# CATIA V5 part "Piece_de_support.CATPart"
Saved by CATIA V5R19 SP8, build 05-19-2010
Part number: Piece_de_support
Bounding box of the stored display mesh (mm): x -170 to 170, y -44 to 314.998, z 1111.393 to 1414.998
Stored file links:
  G:\EU_thinkMotion\CFAO_2010\MMS_groupe2\MMS_groupe2\OK\nrosalie\nrosalie_cfao_support_d_arme_legere_final\Piece_de_support.CATPart
  G:\EU_thinkMotion\CFAO_2010\MMS_groupe2\MMS_groupe2\OK\nrosalie\nrosalie_cfao_support_d_arme_legere_final\nrosalie_Support_d_arme_legere.CATProduct
  G:\EU_thinkMotion\CFAO_2010\MMS_groupe2\MMS_groupe2\OK\nrosalie\nrosalie_cfao_support_d_arme_legere_final\Squelette_Colone.CATPart
  G:\EU_thinkMotion\CFAO_2010\MMS_groupe2\MMS_groupe2\OK\nrosalie\nrosalie_cfao_support_d_arme_legere_final\NAO_40x55x17_PART2.CATPart
  G:\EU_thinkMotion\CFAO_2010\MMS_groupe2\MMS_groupe2\OK\nrosalie\nrosalie_cfao_support_d_arme_legere_final\NKX_45_PART1.CATPart
  G:\EU_thinkMotion\CFAO_2010\MMS_groupe2\MMS_groupe2\OK\nrosalie\nrosalie_cfao_support_d_arme_legere_final\Entretoise_d_usure.CATPart
  G:\EU_thinkMotion\CFAO_2010\MMS_groupe2\MMS_groupe2\OK\nrosalie\nrosalie_cfao_support_d_arme_legere_final\Squelette_Systeme_de_visee.CATPart
  G:\EU_thinkMotion\CFAO_2010\MMS_groupe2\MMS_groupe2\OK\nrosalie\nrosalie_cfao_support_d_arme_legere_final\Squelette_piece_support.CATPart
  G:\EU_thinkMotion\CFAO_2010\MMS_groupe2\MMS_groupe2\OK\nrosalie\nrosalie_cfao_support_d_arme_legere_final\Squelette_systeme_d_equilibrage.CATPart
  C:\Program Files\Dassault Systemes\B19\intel_a\startup\materials\French\Catalog.CATMaterial
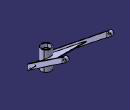
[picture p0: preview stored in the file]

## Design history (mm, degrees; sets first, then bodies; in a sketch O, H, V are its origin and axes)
Set1
  Sketch1 on zx-plane, origin (0, 0, 0), H (-1, 0, 0), V (0, 0, 1)
    line L1 (27.5, 1249) -> (27.5, 1223)
    line L2 (27.5, 1223) -> (25.7071, 1223)
    line L3 (25, 1222.2929) -> (25, 1130.1001)
    line L4 (25.7071, 1129.393) -> (29, 1129.393)
    line L5 (29, 1129.393) -> (29, 1112.1001)
    line L6 (29.7071, 1111.393) -> (34, 1111.393)
    point P4 (34, 1111.393)
    line L7 (27.5, 1249) -> (34, 1249)
    line L8 (34, 1249) -> (34, 1111.393)
    point P6 (34, 1111.393)
    reference projected line E1 (0, 0) -> (0, 1300) from Line1
    line L9 (25.7071, 1223) -> (25, 1222.2929)
    line L10 (25, 1130.1001) -> (25.7071, 1129.393)
    line L11 (29, 1112.1001) -> (29.7071, 1111.393)
    reference projected line E2 (0, 0) -> (0, 1300) from Line1
    reference projected line E3 (0, 0) -> (0, 1300) from Line1
    reference intersected line E4 through (0, 1250) direction (-1, 0) from Plane1
    reference intersected line E5 through (0, 1223) direction (-1, 0) from face of DatumSurface1
    reference intersected line E6 through (0, 1129.393) direction (1, 0) from face of DatumSurface2
    reference intersected line E7 through (0, 1111.393) direction (1, 0) from face of DatumSurface3
    distance L3 E1 = 25
    angle L2 L9 = 45
    length L9 = 1
    angle L3 L10 = 45
    length L10 = 1
    angle L5 L11 = 45
    length L11 = 1
    distance L5 E2 = 29
    distance L1 E3 = 27.5
    distance L8 L5 = 5
    distance L7 E4 = 1
    vertical: L1 V, L3 V, L5 V, L8 V
    horizontal: L2 H, L4 H, L6 H, L7 H
    coincidence: P4 P6, L2 E5, L4 E6, L6 E7
Set2
  Plane1 "Plan_limite_superieur_colonne": linked copy from another document
  DatumSurface1 to DatumSurface3: linked copy from another document
  Line1 "Axe_vertical_colonne": linked copy from another document
  Point1 "Centre_plan_limite_superieur_colonne": linked copy from another document
  DatumCurve1: linked copy from another document
  Plane2: linked copy from another document
  Line2: linked copy from another document
  Line3 "Axe_de_rotation_en_site": linked copy from another document
  Plane3 "Interphase_pivot_permettant _la_rotation_en_site": linked copy from another document
  Point2 "Centre_cou_du_servant": linked copy from another document
  Point3 "Centre_liaison_pivot__systeme_de_visee": linked copy from another document
  Plane4: linked copy from another document
  Point4: linked copy from another document
  Point5 "intersection_axe_colone_et_axe_viseur": linked copy from another document
  Line4: linked copy from another document
  Plane5 "Plan_horizontal_median_viseur": linked copy from another document
  Point6: linked copy from another document
  Line5: linked copy from another document
Body1 (main body)
  Shaft1: profile Sketch1, axis edge of Line1, angle 360
  Sketch2 on zx-plane, origin (0, 0, 0), H (-1, 0, 0), V (0, 0, 1)
    circle A1 centre (-0.0003, 1120.393) radius 0.79
    reference projected circle E1 centre (-0.0003, 1120.393) radius 0.79 from edge of DatumCurve1
    coincidence: E1 A1
  Pocket1: profile Sketch2, direction (0, 1, 0), length 2000
  Sketch3 on yz-plane, origin (0, 0, 0), H (0, 1, 0), V (0, 0, 1)
    line L1 (309, 1388) -> (-44, 1123.25)
    point P1 (-44, 1123.25)
    point P2 (-44, 1123.25)
    line L2 (-44, 1160.75) -> (291, 1412)
    reference projected line E1 (11.8125, 1183.8594) -> (396, 1472) from Line2
    arc A1 centre (300, 1400) radius 15 from (309, 1388) to (291, 1412) ccw
    reference projected point E2 (300, 1400) from Point2
    line L3 (-44, 1160.75) -> (-44, 1123.25)
    reference projected point E3 (0, 1175) from Point3
    radius A1 = 15
    distance E3 L3 = 44
    coincidence: P2 L1, P2 P1
    parallelism: L2 L1
    symmetry: L2 L1 E1
    concentricity: A1 E2
    tangency: L2 A1
    vertical: L3 V
  Sketch4 on Plane2, origin (0, 0, 1175), H (1, 0, 0), V (0, 1, 0)
    line L1 (-166.7686, 285) -> (-85.1019, -65)
    point P2 (-85.1019, -65)
    line L2 (-76, -60) -> (-156.5, 285)
    point P3 (-76, -60)
    point P4 (-156.5, 285)
    line L3 (-166.7686, 285) -> (-170, 285)
    line L4 (-170, 285) -> (-170, 315)
    line L5 (-170, 315) -> (-150, 315)
    line L6 (-150, 315) -> (-150, 285)
    line L7 (-156.5, 285) -> (-150, 285)
    point P9 (-156.5, 285)
    reference projected line E1 (-500, 300) -> (500, 300) from Line3
    reference projected line E2 (-500, 300) -> (500, 300) from Line3
    reference projected line E3 (-88.8296, -5.016) -> (-160, 300) from Line2
    reference intersected line E4 through (-150, 0) direction (0, 1) from Plane3
    reference projected point E5 (0, 0) from Point5
    line L8 (150, 315) -> (150, 285)
    line L9 (150, 285) -> (156.5, 285)
    line L10 (156.5, 285) -> (76, -60)
    point P13 (76, -60)
    point P14 (85.1019, -65)
    line L11 (85.1019, -65) -> (166.7686, 285)
    point P15 (166.7686, 285)
    line L12 (166.7686, 285) -> (170, 285)
    line L13 (170, 315) -> (170, 285)
    line L14 (170, 315) -> (150, 315)
    reference projected line E6 (0, 300) -> (0, 0) from Line4
    reference projected point E7 (0, 300) from Point2
    reference projected line E9 (0, 300) -> (0, 0) from Line4
    reference projected line E10 (0, 300) -> (0, 0) from Line4
    reference projected line E11 (0, 300) -> (0, 0) from Line4
    reference projected line E12 (0, 300) -> (0, 0) from Line4
    reference projected line E13 (0, 300) -> (0, 0) from Line4
    line L15 (-76, -60) -> (76, -60)
    reference projected line E14 (0, 300) -> (0, 0) from Line4
    line L16 (-85.1019, -65) -> (85.1019, -65)
    distance L5 E2 = 15
    distance L4 L6 = 20
    distance L1 L2 = 10
    distance E5 P3 V = 60
    distance L16 L15 = 5
    horizontal: L3 H, L5 H, L7 H, L9 H, L12 H, L14 H, L15 H, L16 H
    vertical: L4 V, L8 V, L13 V
    coincidence: P9 L2, P9 P4, L3 L7, L2 E3, L6 E4, P15 L9
    symmetry: L5 L7 E1, L13 L4 E6, L10 L2 E9, L11 L1 E10, L12 L3 E11, L14 L5 E12, P13 P3 E13, P14 P2 E14
    equidistance: L8 L6 E7
  SolidCombine1: FirstComponentProfile Sketch3, FirstComponentDirection Sketch3, SecondComponentProfile Sketch4, SecondComponentDirection Sketch4
  Sketch5 on Plane2, origin (0, 0, 1175), H (1, 0, 0), V (0, 1, 0)
    line L1 (90.668, -41.1455) -> (-90.668, -41.1455)
    line L2 (-90.668, -41.1455) -> (-137.6019, 160)
    line L3 (-137.6019, 160) -> (137.6019, 160)
    reference projected line E1 (-91.1332, -39.1517) -> (-166.72, 284.7918) from edge [face of SolidCombine1 from Sketch3.L2 | face of SolidCombine1 from Sketch4.L1]
    reference projected point E2 (0, 0) from Point1
    line L4 (137.6019, 160) -> (90.668, -41.1455)
    reference projected line E3 (0, 300) -> (0, 0) from Line4
    reference projected point E4 (0, 0) from Point5
    distance E2 L3 = 160
    distance E4 L1 = 41.1455
    horizontal: L1 H, L3 H
    coincidence: L2 E1
    symmetry: L4 L2 E3
  Sketch6 on yz-plane, origin (0, 0, 0), H (0, 1, 0), V (0, 0, 1)
    line L1 (209.2881, 1328.8411) -> (-42.3111, 1140.1417)
    point P2 (-42.3111, 1140.1417)
    line L2 (-42.3111, 1140.1417) -> (-45.3111, 1144.1417)
    point P3 (-42.3111, 1140.1417)
    line L3 (-45.3111, 1144.1417) -> (390.7119, 1471.1589)
    line L4 (390.7119, 1471.1589) -> (209.2881, 1328.8411)
    reference projected line E1 (11.8125, 1183.8594) -> (396, 1472) from Line2
    reference projected line E2 (11.8125, 1183.8594) -> (396, 1472) from Line2
    reference projected point E3 (300, 1400) from Point2
    reference projected point E4 (0, 1175) from Point3
    distance E2 L3 = 2.5
    distance L2 E4 = 54.7638
    coincidence: P3 L1, P3 P2, L4 E3
    symmetry: L3 L1 E1
    parallelism: L3 L1
    perpendicularity: L2 L3
  SolidCombine2: FirstComponentProfile Sketch5, FirstComponentDirection Sketch5, SecondComponentProfile Sketch6, SecondComponentDirection Sketch6
  Sketch7 on face of SolidCombine1 from Sketch4.L4, origin (-170, 0, 0), H (0, -1, 0), V (0, 0, 1)
    circle A1 centre (-300, 1400) radius 7.5
    reference projected point E1 (-300, 1400) from Point2
    radius A1 = 7.5
    concentricity: A1 E1
  Pocket2: profile Sketch7, direction (1, 0, 0), up to face of SolidCombine1 from Sketch4.L6
  Plane6: type OffsetPt, RefPlane xy-plane, RefPoint Point4
  Sketch8 on Plane6, origin (0, 0, 1197.5), H (1, 0, 0), V (0, 1, 0)
    line L1 (-98.1667, 35) -> (-142, 35)
    point P1 (-98.1667, 35)
    line L2 (-142, 35) -> (-142, 30)
    line L3 (-142, 30) -> (-97, 30)
    line L4 (-97, 30) -> (-98.1667, 35)
    point P5 (-98.1667, 35)
    reference projected line E1 (-90, 0) -> (-160, 300) from Line2
    reference projected point E2 (-127, 30) from Point4
    reference projected point E3 (-127, 30) from Point4
    distance L2 E2 = 15
    distance L1 L3 = 5
    horizontal: L1 H, L3 H
    vertical: L2 V
    coincidence: L4 P1, L4 E1, L3 E3, P5 P1
  Shaft2: profile Sketch8, axis Sketch8.L3, angle 360
  Sketch9 on Plane2, origin (0, 0, 1175), H (1, 0, 0), V (0, 1, 0)
    circle A1 centre (0, 0) radius 25
    reference projected circle E1 centre (0, 0) radius 34 from edge [face of Shaft1 from Sketch1.L8 | face of Shaft1 from Sketch1.L7]
    reference projected circle E2 centre (0, 0) radius 25 from edge [face of Shaft1 from Sketch1.L3 | face of Shaft1 from Sketch1.L10]
    concentricity: E1 A1
    coincidence: A1 E2
  Pocket3: profile Sketch9, direction (0, 0, -1), up to Plane5, opposite side up to xy-plane
  Sketch10 on face of SolidCombine1 from Sketch4.L8, origin (150, 0, 0), H (0, -1, 0), V (0, 0, 1)
    circle A1 centre (-300, 1400) radius 7.5
    reference projected circle E1 centre (-300, 1400) radius 7.5 from edge [face of SolidCombine1 from Sketch4.L4 | face of Pocket2 from Sketch7.A1]
    coincidence: A1 E1
  Pocket4: profile Sketch10, direction (1, 0, 0), up to face of SolidCombine1 from Sketch4.L13
  Sketch11 on Plane6, origin (0, 0, 1197.5), H (1, 0, 0), V (0, 1, 0)
    point P1 (98.1667, 35)
    line L1 (98.1667, 35) -> (142, 35)
    line L2 (142, 35) -> (142, 30)
    line L3 (142, 30) -> (97, 30)
    point P4 (97, 30)
    reference projected point E1 (127, 30) from Point6
    reference projected point E2 (127, 30) from Point6
    reference projected line E3 (160, 300) -> (90, 0) from Line5
    reference projected line E4 (160, 300) -> (90, 0) from Line5
    line L4 (98.1667, 35) -> (97, 30)
    distance L2 E1 = 15
    length L2 = 5
    horizontal: L1 H, L3 H
    vertical: L2 V
    coincidence: L3 E2, P1 E3, P4 E4
  Shaft3: profile Sketch11, axis Sketch11.L3, angle 360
